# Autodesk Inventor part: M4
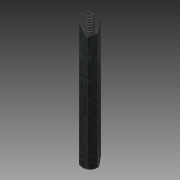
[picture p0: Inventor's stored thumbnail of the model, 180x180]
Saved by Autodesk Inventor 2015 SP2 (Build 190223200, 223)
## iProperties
Created: 2012-08
Part Number: M4
Material: Stahl
Document SubType Name: Modeling
Designer: rYan
Density: 7.85 g/cm^3
Mass: 3.36246 g
Surface Area: 5.74911 cm^2
Volume: 0.428339 cm^3
Appearance: Platte
Author: rYan
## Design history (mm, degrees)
derived "Abstandsbolzen Typ A.ipt"
feature "Volumenkörper1::Abstandsbolzen Typ A.ipt"
tag "Bezeichnung1"
node "Volumenkörper1"
other parameters: "SW" = 7, "L" = 65, "d2" = 0, "d16" = 45 deg
